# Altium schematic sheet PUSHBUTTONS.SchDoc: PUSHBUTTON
size A3; Author: Silvio Navaretti; CompanyName: ARDUINO; DrawnBy: Silvio Navaretti; Engineer: Silvio Navaretti; Organization: ARDUINO; SheetNumber: 49; SheetTotal: 51; RevAuthor: Silvio Navaretti
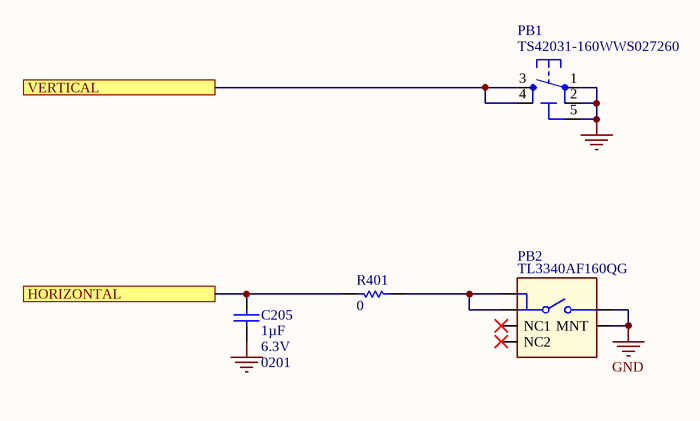
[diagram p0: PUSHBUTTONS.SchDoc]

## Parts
C205  value 1µF  Voltage: 6.3V  Case Code (Imperial): 0201  [CAP-0201]  (hidden comment: GRM033R60J105MEA2D)
PB1  TS42031-160WWS027260  [TS42]
PB2  TL3340AF160QG  [TL3340AF160QG-Footprint-1]
R401  value 0  [RES-0201]  (hidden comment: CRCW02010000Z0ED)

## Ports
HORIZONTAL, VERTICAL

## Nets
GND: C205.1 PB1.1 PB1.2 PB1.5(5-GND) PB2.2 PB2.MNT
HORIZONTAL: C205.2 R401.1 ; port HORIZONTAL
VERTICAL: PB1.3 PB1.4 ; port VERTICAL
NetPB2_1: PB2.1 PB2.3 R401.2

Not connected (* = marked no-connect by the designer): PB2 NC1* NC2*

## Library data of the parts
C205 = C0002-A.15: CAP CHIP 0201 1uF 20% 6.3V X5R; Manufacturer: Murata; Code Arduino: A5520
PB1 = B0005-A.11: PUSHBUTTON SMD 6x6 5 PINS; Manufacturer: C&K; Code Arduino: 0946
PB2 = B0013-A.8: PUSHBUTTON SMD VERTICAL ANCHORS 4x3.4mm; Manufacturer: E-Switch; Code Arduino: B0013
R401 = R0140-A.21: RES CHIP 0201 0R; Manufacturer: Vishay; Tolerance: 0%; Temperature coefficient: 0ppm; Power: 50mW; Code Arduino: R0140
